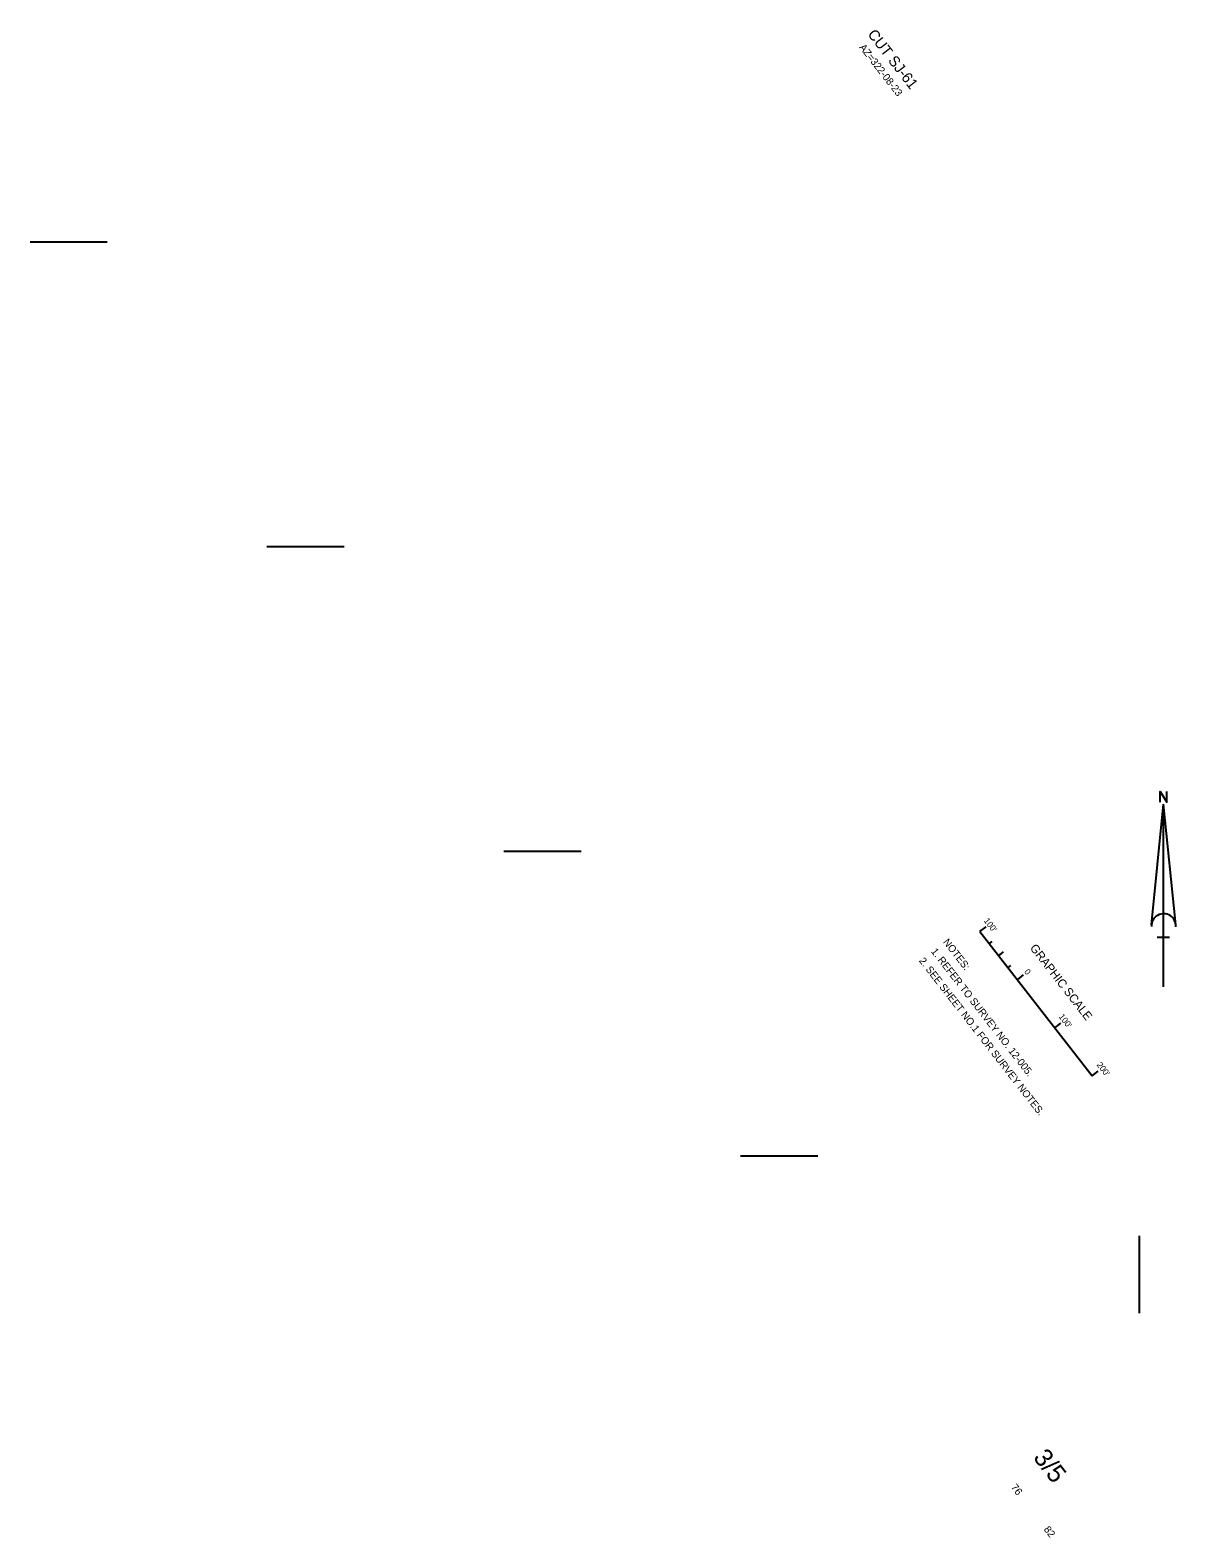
# Model space of a CAD drawing. Extents: x 576902 to 581733, y 1952373 to 1957293.
# Drawn here: x 577680 to 579560, y 1952373 to 1954847 of the extents above; entities that cross this region are included whole.
import ezdxf

# ---------------------------------------------------------------- set-up
doc = ezdxf.new("R2010")
doc.units = 0
for name, color, linetype in [('V-ANNO-KEYN', 7, 'Continuous'), ('V-ANNO-NOTE', 7, 'Continuous'), ('V-ANNO-NPLT', 7, 'Continuous'), ('V-COMM-OVHD', 7, 'Continuous'), ('V-DUCT-MULT-IDEN', 7, 'Continuous')]:
    doc.layers.add(name, color=color, linetype=linetype)

msp = doc.modelspace()

# ---------------------------------------------------------------- linework, layer by layer
at = {"layer": 'V-ANNO-NOTE'}
for p, q in [((579520.1, 1953379.4), (579540, 1953577.4)), ((579540, 1953277.4), (579540, 1953577.4)), ((579559.9, 1953379.4), (579540, 1953577.4)), ((579238.6, 1953368.1), (579248.5, 1953375.8)), ((579238.6, 1953368.1), (579422.8, 1953131.2)), ((579254.2, 1953348.5), (579258.7, 1953352.1)), ((579549.5, 1953358.4), (579529.5, 1953358.4)), ((579269.3, 1953328.6), (579277.4, 1953334.9)), ((579269.5, 1953328.8), (579274, 1953332.3)), ((579284.8, 1953309), (579289.4, 1953312.6)), ((579300, 1953289.2), (579309.9, 1953296.9)), ((579300, 1953289.2), (579309.9, 1953296.9)), ((579300, 1953289.2), (579304.7, 1953292.8)), ((579361.4, 1953210.2), (579371.3, 1953217.9)), ((579422.7, 1953131.3), (579432.6, 1953138.9))]:
    msp.add_line(p, q, dxfattribs=at)
msp.add_lwpolyline([(579534.5, 1953580.6), (579534.5, 1953598.1), (579545.4, 1953580.6), (579545.4, 1953598.1)], dxfattribs=at)
msp.add_arc((579540, 1953377.4), 20, 355.2984, 182.0673, dxfattribs=at)
at = {"layer": 'V-DUCT-MULT-IDEN'}
for p, q in [((577679.8, 1954500), (577806.4, 1954500)), ((578068.4, 1954000), (578195.1, 1954000)), ((578457.1, 1953500), (578583.8, 1953500)), ((578845.8, 1953000), (578972.5, 1953000)), ((579500, 1952868.8), (579500, 1952742.2))]:
    msp.add_line(p, q, dxfattribs=at)

# ---------------------------------------------------------------- texts
at = {"layer": 'V-ANNO-KEYN'}
for s, height, p in [('  3/5 ', 30, (579311.1, 1952522.2)), (' 76 ', 12, (579286, 1952459.6)), (' 82 ', 12, (579339.9, 1952390.3))]:
    msp.add_text(s, height=height, rotation=307.8605, dxfattribs=at).set_placement(p)
at = {"layer": 'V-ANNO-NOTE'}
for s, height, p in [("100'", 10, (579244.3, 1953385.7)), ('GRAPHIC SCALE', 14, (579319.7, 1953341)), ('0', 10, (579310.5, 1953301.9)), ("100'", 10, (579367.2, 1953228.4)), ("200'", 10, (579429.5, 1953149.3))]:
    msp.add_text(s, height=height, rotation=307.8605, dxfattribs=at).set_placement(p)
at = {"layer": 'V-ANNO-NPLT'}
for s, p in [('NOTES:', (579177.3, 1953350.7)), ('2. SEE SHEET NO.1 FOR SURVEY NOTES.', (579137.8, 1953320)), ('1. REFER TO SURVEY NO. 12-005.', (579157.5, 1953335.4))]:
    msp.add_text(s, height=12, rotation=307.8605, dxfattribs=at).set_placement(p)
at = {"layer": 'V-COMM-OVHD'}
for s, height, p in [('CUT SJ-61', 17.52, (579053.3, 1954840.3)), ('AZ=322-08-23', 12, (579039.8, 1954819))]:
    msp.add_text(s, height=height, rotation=307.8605, dxfattribs=at).set_placement(p)

doc.saveas('drawing.dxf')
